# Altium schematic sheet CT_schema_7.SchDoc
size 277 x 170 mm
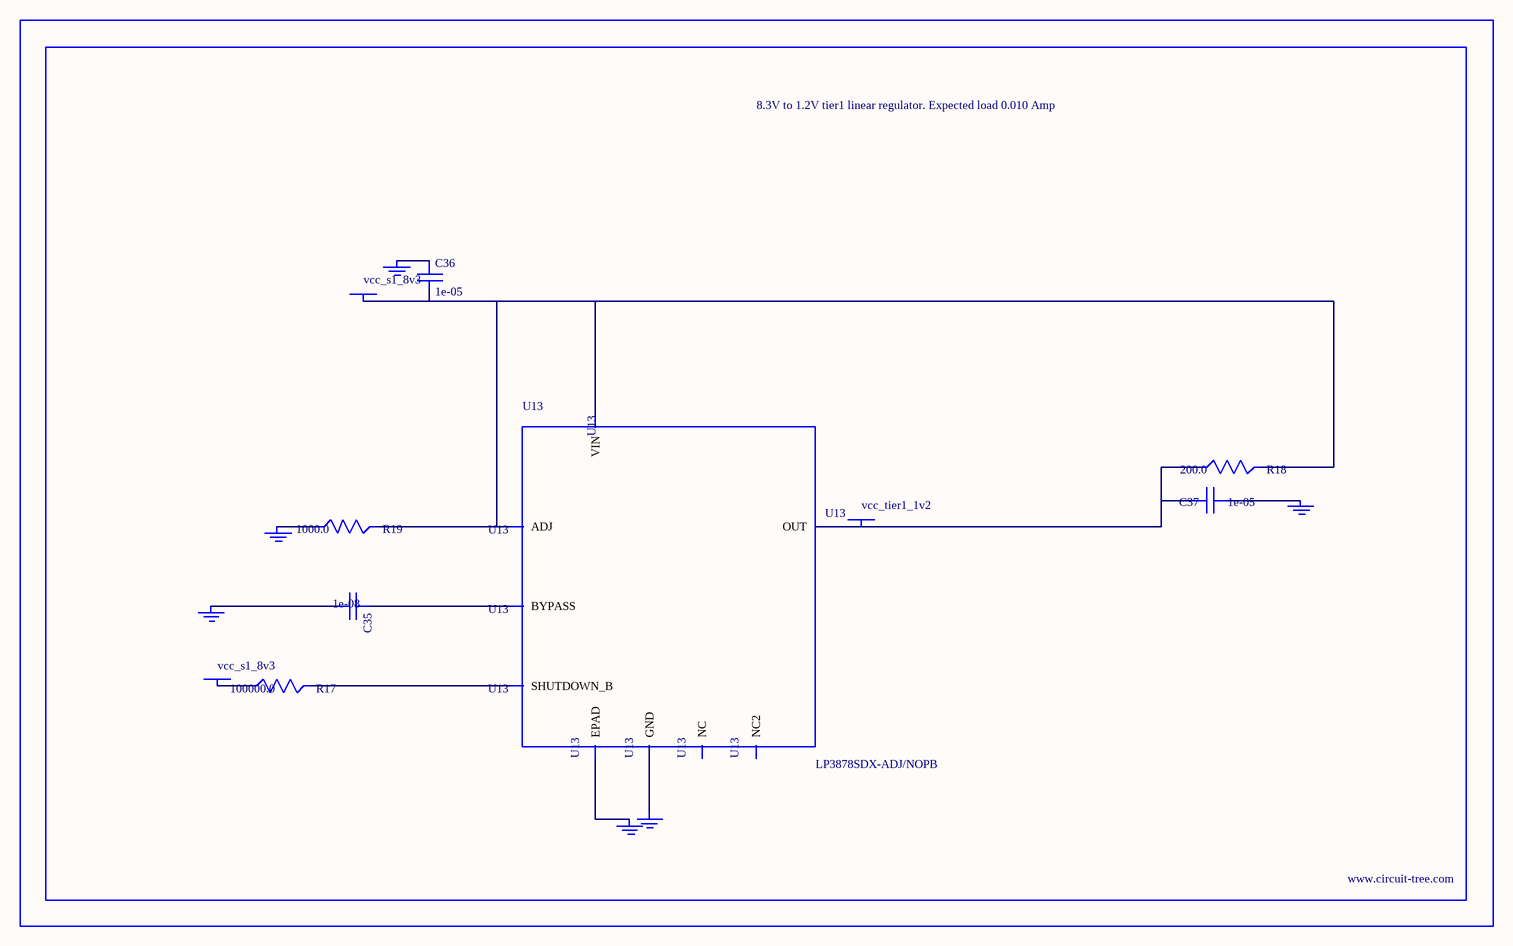
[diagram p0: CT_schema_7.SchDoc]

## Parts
BORDER6  (no value)
C35  1e-08  [C0402]
C36  1e-05  [C1206]
C37  1e-05  [C0805]
GND_INSTANCE_6_0  (no value)
GND_INSTANCE_6_1  (no value)
GND_INSTANCE_6_2  (no value)
GND_INSTANCE_6_3  (no value)
GND_INSTANCE_6_4  (no value)
GND_INSTANCE_6_5  (no value)
POWER_INSTANCE_6_0  vcc_s1_8v3
POWER_INSTANCE_6_1  vcc_s1_8v3
POWER_INSTANCE_6_2  vcc_tier1_1v2
R17  100000.0  [R0603]
R18  200.0  [R0603]
R19  1000.0  [R0603]
U13  LP3878SDX-ADJ/NOPB  [WSON-8]

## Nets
NetC35_1: C35.1 U13.1(BYPASS)
NetC35_2: C35.2 GND_INSTANCE_6_0.0(GND)
NetC36_1: C36.1 GND_INSTANCE_6_1.0(GND)
NetC36_2: C36.2 POWER_INSTANCE_6_0.0(PWR) R18.2 R19.2 U13.4(VIN) U13.6(ADJ)
NetC37_1: C37.1 GND_INSTANCE_6_2.0(GND)
NetC37_2: C37.2 POWER_INSTANCE_6_2.0(PWR) R18.1 U13.5(OUT)
NetGND_INSTANCE_6_3_0: GND_INSTANCE_6_3.0(GND) R19.1
NetGND_INSTANCE_6_4_0: GND_INSTANCE_6_4.0(GND) U13.PAD(EPAD)
NetGND_INSTANCE_6_5_0: GND_INSTANCE_6_5.0(GND) U13.3(GND)
NetPOWER_INSTANCE_6_1_0: POWER_INSTANCE_6_1.0(PWR) R17.1
NetR17_2: R17.2 U13.8(SHUTDOWN_B)

Not connected (* = marked no-connect by the designer): U13 2(NC) 7(NC2)

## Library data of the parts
BORDER6 = BORDER_PAGE6
C35 = C0402C103K3RAC
C36 = C1206C106K3RACTU
C37 = GRM219R60J106ME19D
GND_INSTANCE_6_0-GND_INSTANCE_6_5 = GND
POWER_INSTANCE_6_0-POWER_INSTANCE_6_2 = PWR
R17 = RC0603JR-07100KL
R18 = RC0603JR-07200RL
R19 = RC0603JR-071KL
